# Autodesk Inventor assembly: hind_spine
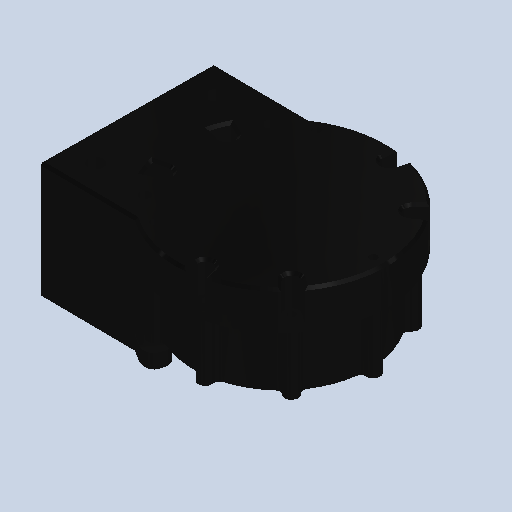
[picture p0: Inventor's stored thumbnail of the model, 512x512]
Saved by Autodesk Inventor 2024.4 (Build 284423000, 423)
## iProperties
Created: 2026-01
Part Number: hind_spine
Document SubType Name: Assembly
Designer: AdminForWorker
Title: hind_spine v1
Author: AdminForWorker
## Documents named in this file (4)
- c:\worker\convert-fusion-r06-cosv3\tmp\job-1\20\temp\files\5a45f03c-e7c3-4700-b116-8c6d3caf3368\hind_spine v1.iam
- c:\worker\convert-fusion-r06-cosv3\tmp\job-1\20\temp\files\5a45f03c-e7c3-4700-b116-8c6d3caf3368\CyberGear_1.ipt
- c:\worker\convert-fusion-r06-cosv3\tmp\job-1\20\temp\files\5a45f03c-e7c3-4700-b116-8c6d3caf3368\body_split1.ipt
- c:\worker\convert-fusion-r06-cosv3\tmp\job-1\20\temp\files\5a45f03c-e7c3-4700-b116-8c6d3caf3368\front_body.ipt
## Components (3 placed, 3 different names)
1. CyberGear:1
2. body_split1:1
3. front_body:1
